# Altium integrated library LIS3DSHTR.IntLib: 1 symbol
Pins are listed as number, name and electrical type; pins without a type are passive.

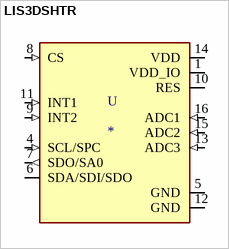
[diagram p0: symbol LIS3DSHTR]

## LIS3DSHTR
designator U
Accelerometer X, Y, Z Axis Â±2g, 4g, 6g, 8g, 16g 1.56Hz ~ 800Hz 16-LGA _3x3_; MP: LIS3DSHTR; MF: STMicroelectronics
footprint LGA16R50P5X3_300X300X100N
pins: 1 VDD_IO (power), 4 SCL/SPC (in), 5 GND (power), 6 SDA/SDI/SDO (io), 7 SDO/SA0 (out), 8 CS (in), 9 INT2 (in), 10 RES (power), 11 INT1 (in), 12 GND (power), 13 ADC3 (in), 14 VDD (power), 15 ADC2 (in), 16 ADC1 (in)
